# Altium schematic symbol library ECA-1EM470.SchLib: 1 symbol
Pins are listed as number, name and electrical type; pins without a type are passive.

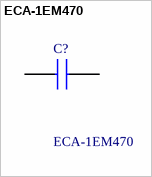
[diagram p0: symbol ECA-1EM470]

## ECA-1EM470
designator C?
PANASONIC - ECA-1EM470 - ALUMINUM ELECTROLYTIC CAPACITOR, 47UF, 20%, 25V, RADIAL; Geometry.Height: 12mm
footprint CAPPRD200W55D500H1200
pins: 1 +, 2 -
